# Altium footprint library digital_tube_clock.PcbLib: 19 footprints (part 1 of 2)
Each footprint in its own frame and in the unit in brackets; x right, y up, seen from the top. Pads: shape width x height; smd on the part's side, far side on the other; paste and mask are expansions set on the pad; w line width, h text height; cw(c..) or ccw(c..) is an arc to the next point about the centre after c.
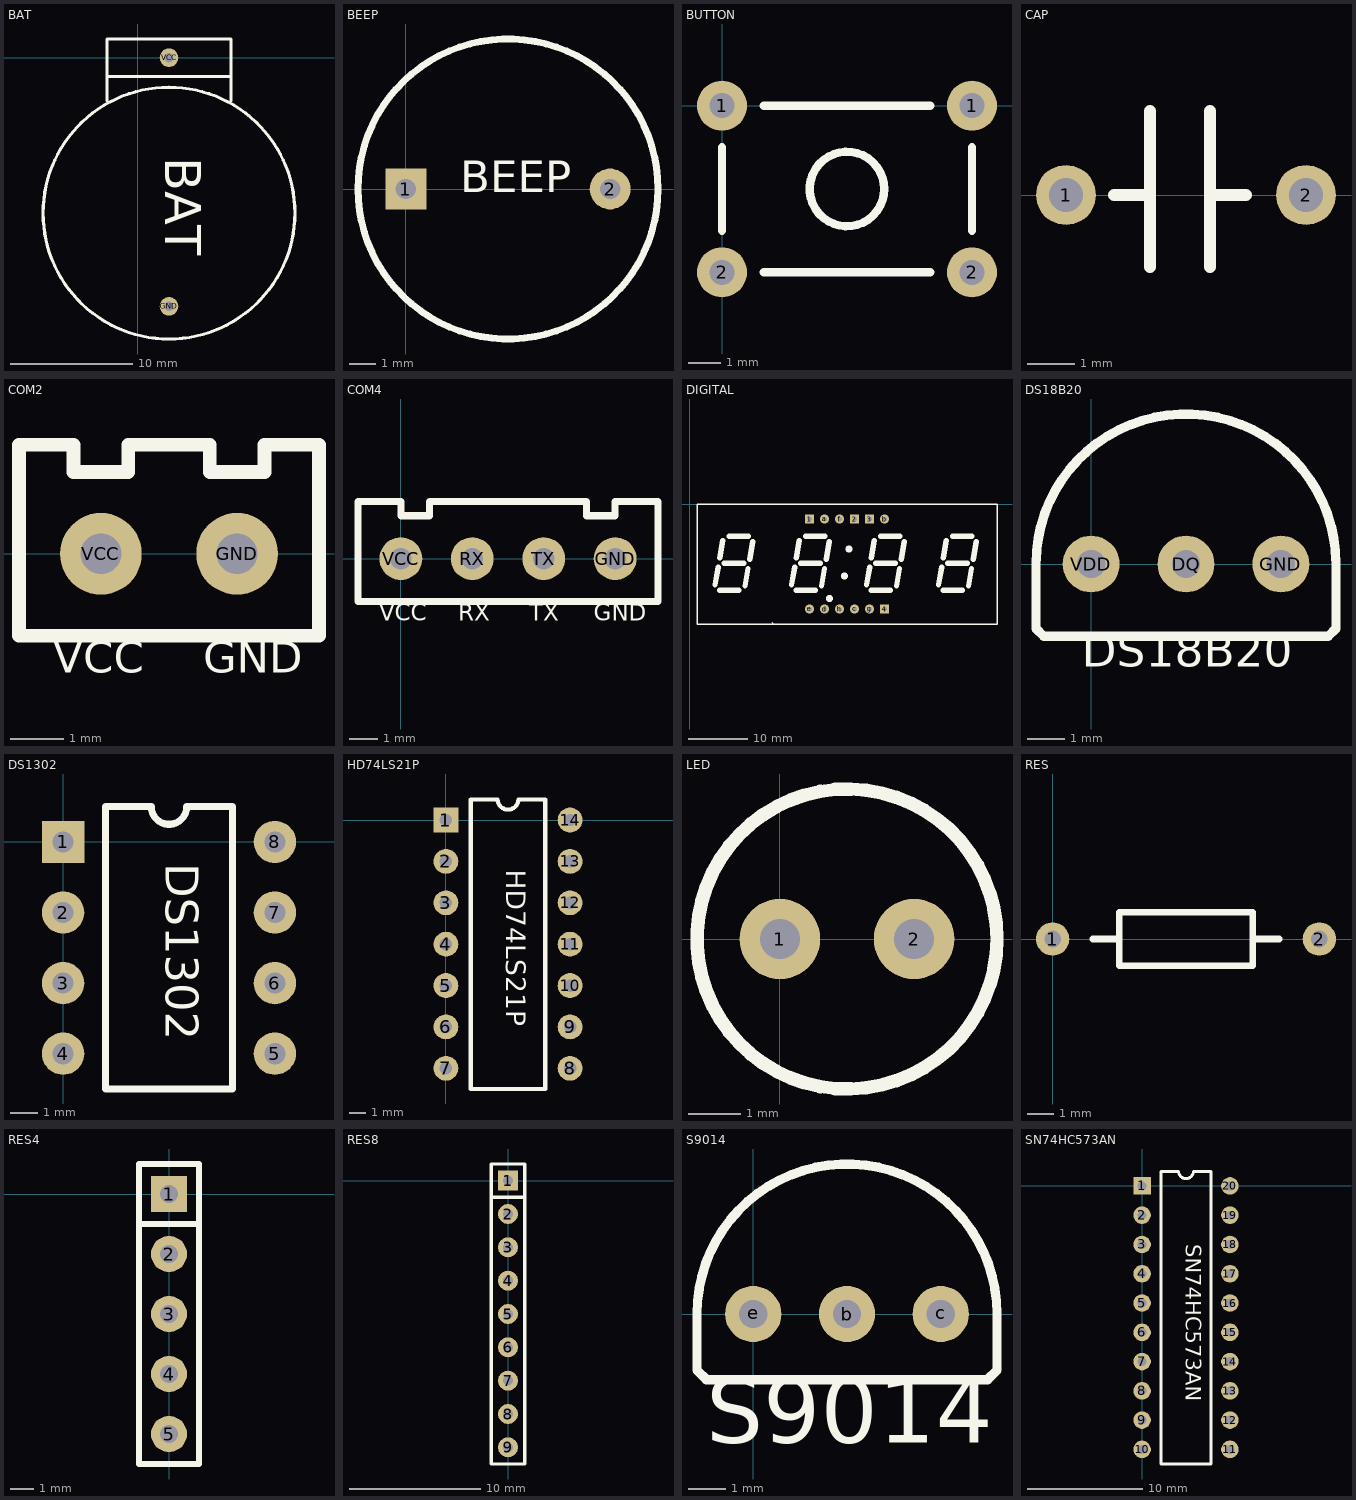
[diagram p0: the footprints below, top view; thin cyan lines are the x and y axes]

## BAT [mil]
pads (2):
  round 60 hole 30: GND(100,-800) VCC(100,0)
Top Overlay:
  circle w10: c100,-500 r404.97
  lines w10: -100,-140 -100,60 300,60 300,-120 300,-140 ; -100,-60 300,-60
  text "BAT" at 50,-320 h200

## BEEP [mil]
pads (2):
  rect 60x60 hole 30: 1(0,0)
  round 60 hole 30: 2(300,0)
Top Overlay:
  circle w10: c150,0 r220.23
  text "BEEP" at 80,-20 h80

## BUTTON [mil]
pads (4):
  round 60 hole 30: 1(0,0) 1(300,0) 2(0,-200) 2(300,-200)
Top Overlay:
  circle w10: c150,-100 r44.72
  lines w10: 0,-150 0,-50 ; 50,-200 250,-200 ; 50,0 250,0 ; 300,-150 300,-50

## CAP [mil]
pads (2):
  round 50 hole 28: 1(100,0) 2(300,0)
Top Overlay:
  lines w10: 140,0 150,0 170,0 ; 170,-60 170,0 ; 170,70 170,0 ; 220,-60 220,0 ; 220,70 220,0 ; 250,0 220,0

## COM2 [mil]
pads (2):
  round 60 hole 30: GND(200,0) VCC(100,0)
Top Overlay:
  lines w10: 40,-60 40,0 40,80 80,80 80,60 120,60 120,80 180,80 180,60 220,60 220,80 260,80 260,-60 40,-60
  text "GND" at 175,-95 h40
  text "VCC" at 65,-95 h40

## COM4 [mil]
pads (4):
  round 60 hole 30: GND(300,0) RX(100,0) TX(200,0) VCC(0,0)
Top Overlay:
  lines w10: -60,-60 360,-60 360,0 360,80 300,80 300,60 260,60 260,80 40,80 40,60 0,60 0,80 -60,80 -60,0 -60,-60
  text "VCC" at -30,-95 h40
  text "RX" at 80,-95 h40
  text "TX" at 180,-95 h40
  text "GND" at 270,-95 h40

## DIGITAL [mil] "LED, 7-Segment Display, 10 mm, Three Digit; 15 Leads (4 Absent); Row Space 10.16 mm; Pitch 2.54 mm"
height 285.43
pads (12):
  rect 60x60 hole 30: 1(800,-100) 2(1100,-100) 3(1200,-100) 4(1300,-700)
  round 60 hole 30: a(900,-100) b(1300,-100) c(1100,-700) d(900,-700) e(800,-700) f(1000,-100) g(1200,-700) h(1000,-700)
Top Overlay:
  circle w33.86: c1063.31,-300 r6.69
  circle w33.86: c1033.31,-480 r6.69
  circle w33.86: c933.31,-630 r6.69
  lines w10: 550,-790 560,-800 ; 50,-800 50,0 2050,0 2050,-700 2050,-800 50,-800
  lines w35.43: 170.02,-538.7 190.88,-422.56 ; 200.25,-574.13 328.68,-574.13 ; 202.3,-359.57 222.38,-243.82 ; 231.83,-395 360.96,-395 ; 263.41,-215.87 392.06,-215.87 ; 370.02,-546.57 390.49,-430.43 ; 401.51,-367.44 421.98,-251.3 ; 680.02,-538.7 700.88,-422.56 ; 710.25,-574.13 838.68,-574.13 ; 712.3,-359.57 732.38,-243.82 ; 741.83,-395 870.96,-395 ; 773.41,-215.87 902.06,-215.87 ; 880.02,-546.57 900.49,-430.43 ; 911.51,-367.44 931.98,-251.3 ; 1180.02,-538.7 1200.88,-422.56 ; 1210.25,-574.13 1338.68,-574.13 ; 1212.3,-359.57 1232.38,-243.82 ; 1241.83,-395 1370.96,-395 ; 1273.41,-215.87 1402.06,-215.87 ; 1380.02,-546.57 1400.49,-430.43 ; 1411.51,-367.44 1431.98,-251.3 ; 1660.02,-538.7 1680.88,-422.56 ; 1690.25,-574.13 1818.68,-574.13 ; 1692.3,-359.57 1712.38,-243.82 ; 1721.83,-395 1850.96,-395 ; 1753.41,-215.87 1882.06,-215.87 ; 1860.02,-546.57 1880.49,-430.43 ; 1891.51,-367.44 1911.98,-251.3

## DS18B20 [mil]
pads (3):
  round 60 hole 30: DQ(100,0) GND(200,0) VDD(0,0)
Top Overlay:
  lines w10: -58.11,-68.11 -58.11,0 cw(c100,0) 258.11,0 258.11,-68.11 250,-76.23 243.77,-76.23 -50,-76.23 -58.11,-68.11
  text "DS18B20" at -10,-120 h60

## DS1302 [mil]
pads (8):
  rect 60x60 hole 30: 1(0,0)
  round 60 hole 30: 2(0,-100) 3(0,-200) 4(0,-300) 5(300,-300) 6(300,-200) 7(300,-100) 8(300,0)
Top Overlay:
  lines w10: 60,-350 240,-350 240,50 175,50 cw(c150,50) 125,50 60,50 60,-350
  text "DS1302" at 130,-30 h80

## HD74LS21P [mil]
pads (14):
  rect 60x60 hole 30: 1(0,0)
  round 60 hole 30: 2(0,-100) 3(0,-200) 4(0,-300) 5(0,-400) 6(0,-500) 7(0,-600) 8(300,-600) 9(300,-500) 10(300,-400) 11(300,-300) 12(300,-200) 13(300,-100) 14(300,0)
Top Overlay:
  lines w10: 60,-650 60,50 125,50 ccw(c150,50) 175,50 240,50 240,-650 60,-650
  text "HD74LS21P" at 130,-120 h80

## LED [mil]
pads (2):
  round 60 hole 30: 1(0,0) 2(100,0)
Top Overlay:
  circle w10: c50,0 r111.8

## RES [mil]
pads (2):
  round 50 hole 25: 1(0,0) 2(400,0)
Top Overlay:
  lines w10: 60,0 100,0 ; 100,0 100,-40 300,-40 300,0 ; 100,0 100,40 300,40 300,0 ; 300,0 340,0 300,0

## RES4 [mil]
pads (5):
  rect 60x60 hole 30: 1(0,0)
  round 60 hole 30: 2(0,-100) 3(0,-200) 4(0,-300) 5(0,-400)
Top Overlay:
  lines w10: -50,-50 50,-50 ; -50,-450 -50,50 50,50 50,-450 -50,-450

## RES8 [mil]
pads (9):
  rect 60x60 hole 30: 1(0,0)
  round 60 hole 30: 2(0,-100) 3(0,-200) 4(0,-300) 5(0,-400) 6(0,-500) 7(0,-600) 8(0,-700) 9(0,-800)
Top Overlay:
  lines w10: -50,-50 50,-50 ; -50,-850 50,-850 50,50 0,50 -50,50 -50,-850

## S9014 [mil]
pads (3):
  round 60 hole 30: b(100,0) c(200,0) e(0,0)
Top Overlay:
  lines w10: -60,-60 -60,0 cw(c100,0) 260,0 260,-60 250,-70 -50,-70 -60,-60
  text "S9014" at -50,-160 h120

## SN74HC573AN [mil]
pads (20):
  rect 60x60 hole 30: 1(0,0)
  round 60 hole 30: 2(0,-100) 3(0,-200) 4(0,-300) 5(0,-400) 6(0,-500) 7(0,-600) 8(0,-700) 9(0,-800) 10(0,-900) 11(300,-900) 12(300,-800) 13(300,-700) 14(300,-600) 15(300,-500) 16(300,-400) 17(300,-300) 18(300,-200) 19(300,-100) 20(300,0)
Top Overlay:
  lines w10: 65,-950 235,-950 235,50 175,50 cw(c150,50) 125,50 65,50 65,-950
  text "SN74HC573AN" at 130,-200 h90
